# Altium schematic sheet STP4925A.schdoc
size 127 x 101 mm
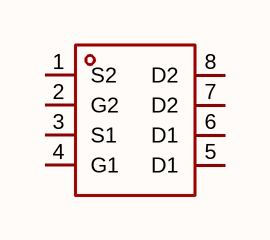
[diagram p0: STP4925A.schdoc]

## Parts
Q?  stp4925a(umw)  [SOP-8_L4.9-W3.9-P1.27-LS6.0-BL]  (value not drawn)

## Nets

Not connected (* = marked no-connect by the designer): Q? 1(S2) 2(G2) 3(S1) 4(G1) 5(D1) 6(D1) 7(D2) 8(D2)

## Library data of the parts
Q? = stp4925a(umw): 数量:2个P沟道;漏源电压(Vdss):30V;连续漏极电流(Id):7.2A;导通电阻(RDS(on)):21mΩ@10V;耗散功率(Pd):2.8W;阈值电压(Vgs(th)):3V;; Manufacturer: UMW(友台半导体); AddInBom: yes; ModelId: 75c24a7891ee4dd6bdac16a7163ff87e; ModelName: SOP-8_L4.9-W3.9-P1.27-LS6.0-BL-1; ModelTransform: 192.913,236.22,0,0,0,0,-0.393,2.749,0; Number: 2个P沟道; Drain to Source Voltage: 30V; Current - Continuous Drain(Id): 7.2A; Pd - Power Dissipation: 2.8W; Gate Threshold Voltage (Vgs(th)): 3V; Gate Charge(Qg): 16nC@10V; Input Capacitance(Ciss): 1.65nF; Reverse Transfer Capacitance (Crss@Vds): 235pF; Type: P沟道; Output Capacitance(Coss): 350pF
